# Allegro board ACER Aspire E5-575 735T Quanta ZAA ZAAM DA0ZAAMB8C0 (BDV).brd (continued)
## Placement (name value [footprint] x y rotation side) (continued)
C4682  gka@0.1u/16v_4  [C0402]  223.07 118.13 180 top
C4683  gka@1u/6.3v_4  [C0402]  208.21 113.3 270 bottom
C4684  gka@1u/6.3v_4  [C0402]  223.07 116.1 0 top
C4685  *gka@0.1u/16v_4  [C0402]  222.94 136.42 180 top
C4686  gka@0.1u/16v_4  [C0402]  212.78 113.3 270 bottom
C4687  gka@0.1u/16v_4  [C0402]  211.64 113.3 270 bottom
C4688  gka@1u/6.3v_4  [C0402]  223.07 119.15 0 bottom
C4689  gka@10u/6.3v_6  [C0603]  222.94 124.1 270 bottom
C4690  gka@1u/6.3v_4  [C0402]  219.64 131.97 0 top
C4691  gka@1u/6.3v_4  [C0402]  208.21 113.3 270 top
C4692  gka@1u/6.3v_4  [C0402]  222.94 147.72 0 top
C4693  gka@1u/6.3v_4  [C0402]  209.48 133.37 180 top
C4694  gka@0.047u/10v_4  [C0402]  223.07 117.11 180 top
C4695  gka@0.047u/10v_4  [C0402]  223.07 126 180 bottom
C4696  gka@0.047u/10v_4  [C0402]  207.45 133.37 0 top
C4697  gka@1u/6.3v_4  [C0402]  217.99 151.66 90 top
C4698  gka@0.1u/16v_4  [C0402]  223.07 127.02 180 top
C4699  gka@0.1u/16v_4  [C0402]  219.39 113.3 90 top
C4700  gka@0.1u/16v_4  [C0402]  215.58 133.37 180 top
C4701  gka@330u/2v_7343  [CC7343]  221.7 112.23 180 bottom
C4702  gka@0.1u/16v_4  [C0402]  215.58 131.97 180 top
C4703  gka@1u/6.3v_4  [C0402]  209.48 131.97 180 top
C4704  gka@0.1u/16v_4  [C0402]  223.07 127.02 180 bottom
C4705  gka@0.1u/16v_4  [C0402]  222.94 147.72 180 bottom
C4706  gka@10u/6.3v_6  [C0603]  223.32 135.02 180 top
C4707  gka@0.1u/16v_4  [C0402]  223.07 126 180 top
C4708  gka@0.047u/10v_4  [C0402]  222.05 131.97 180 top
C4709  *gka@0.1u/16v_4  [C0402]  209.35 113.3 90 top
C4711  100u/6.3v_12  [C1206]  208.34 21.74 90 bottom
C4712  100u/6.3v_1206  [C1206]  208.34 26.44 90 bottom
C4713  470p/50v_4  [C0402]  212.02 26.31 0 bottom
C4714  1u/6.3v_4  [C0402]  215.07 28.34 270 bottom
C4715  0.1u/16v_4  [C0402]  209.99 27.96 90 bottom
C4719  ev@0.1u/16v_4  [C0402]  206.43 157.63 180 top
C4721  ev@22u/6.3v_6  [C0603]  206.81 156.36 180 top
C4723  *22p/50v_4  [C0402]  150.68 101.37 180 bottom
C4726  *22p/50v_4  [C0402]  175.82 47.9 270 bottom
C4732  47u/6.3v_8  [C0805]  91.62 115.21 90 top
C4733  *10p/50v_4  [C0402]  170.24 81.43 270 bottom
C4734  *10u/6.3v_4  [C0402]  169.22 81.43 270 bottom
C4735  *0.1u/16v_4  [C0402]  171.51 81.43 270 bottom
C4736  *10p/50v_4  [C0402]  169.98 83.08 0 bottom
C4737  *10p/50v_4  [C0402]  171.51 84.98 90 bottom
C4748  0.1u/16v_4  [C0402]  28 67.71 0 top
C4749  0.1u/16v_4  [C0402]  21.39 71.14 0 bottom
C4750  0.1u/16v_4  [C0402]  21.65 68.6 0 bottom
C4751  0.1u/16v_4  [C0402]  21.52 63.9 270 top
C4752  0.1u/16v_4  [C0402]  22.54 63.9 270 top
C4753  4.7u/6.3v_4  [C0402]  21.39 72.26 180 bottom
C4754  2.2u/6.3v_4  [C0402]  20.4 63.9 270 top
C4762  tyc@0.1u/25v/x5r_4  [C0402]  21.01 120.67 180 bottom
C4763  tyc@0.1u/25v/x5r_4  [C0402]  21.01 121.56 180 bottom
C4764  tyc@0.1u/25v_4  [C0402]  11.11 116.33 0 top
C4765  tyc@10u/6.3v/x5r_6  [C0603]  28.5 108.73 90 top
C4766  tyc@10u/6.3v/x5r_6  [C0603]  36.76 109.75 0 top
C4767  tyc@0.1u/25v_4  [C0402]  19.49 112.54 90 top
C4768  tyc@0.1u/25v_4  [C0402]  11.11 115.36 0 top
C4769  tyc@10u/6.3v/x5r_6  [C0603]  36.76 108.48 0 top
C4770  tyc@0.1u/25v/x5r_4  [C0402]  21.14 116.73 180 bottom
C4771  tyc@0.1u/25v/x5r_4  [C0402]  21.14 117.62 180 bottom
C4772  tyc@150u/6.3v_3528  [C3528]  37.65 106.06 180 top
C4773  tyc@0.1u/16v_4_x7r  [C0402]  27.23 118.51 0 top
C4774  tyc@0.1u/16v_4_x7r  [C0402]  35.11 120.67 180 top
C4775  tyc@10u/6.3v_6_x5r  [C0603]  27.62 117.37 0 top
C4776  tyc@0.1u/16v_4_x7r  [C0402]  37.52 121.05 0 top
C4777  tyc@0.1u/16v_4_x7r  [C0402]  37.52 120.16 0 top
C4778  tyc@0.1u/16v_4_x7r  [C0402]  37.52 122.83 0 top
C4779  tyc@0.1u/16v_4_x7r  [C0402]  37.52 121.94 0 top
C4780  tyc@0.1u/16v_4_x7r  [C0402]  37.52 118.13 0 top
C4781  tyc@0.1u/16v_4_x7r  [C0402]  35.74 116.99 0 top
C4782  *ioac@0.1u/16v_4  [C0402]  48.57 70.38 90 top
C4783  0.1u/16v_4  [C0402]  22.92 52.09 0 top
C4784  0.1u/16v_4_x7r  [C0402]  17.07 43.33 270 top
C4785  0.1u/16v_4_x7r  [C0402]  20.5 55.14 270 top
C4786  0.1u/16v_4_x7r  [C0402]  18.34 55.14 270 top
C4787  0.1u/16v_4_x7r  [C0402]  22.92 53.87 180 top
C4788  *220p/50v_4  [C0402]  195.66 23.64 270 bottom
C4789  *220p/50v_4  [C0402]  194.52 23.64 270 bottom
C4790  *220p/50v_4  [C0402]  193.35 23.64 270 bottom
C4791  *220p/50v_4  [C0402]  192.21 23.64 270 bottom
C4792  *220p/50v_4  [C0402]  177.35 23.64 270 bottom
C4793  *220p/50v_4  [C0402]  176.21 23.64 270 bottom
C4794  *220p/50v_4  [C0402]  175.06 23.64 270 bottom
C4795  *220p/50v_4  [C0402]  173.92 23.64 270 bottom
C4796  *220p/50v_4  [C0402]  181.92 23.64 270 bottom
C4797  *220p/50v_4  [C0402]  180.78 23.64 270 bottom
C4798  *220p/50v_4  [C0402]  179.63 23.64 270 bottom
C4799  *220p/50v_4  [C0402]  178.49 23.64 270 bottom
C4800  *220p/50v_4  [C0402]  186.49 23.64 270 bottom
C4801  *220p/50v_4  [C0402]  185.35 23.64 270 bottom
C4802  *220p/50v_4  [C0402]  184.21 23.64 270 bottom
C4803  *220p/50v_4  [C0402]  183.06 23.64 270 bottom
C4804  *220p/50v_4  [C0402]  200.23 23.64 270 bottom
C4805  *220p/50v_4  [C0402]  199.07 23.64 270 bottom
C4806  *220p/50v_4  [C0402]  197.95 23.64 270 bottom
C4807  *220p/50v_4  [C0402]  196.78 23.64 270 bottom
C4808  *220p/50v_4  [C0402]  191.06 23.64 270 bottom
C4809  *220p/50v_4  [C0402]  189.92 23.64 270 bottom
C4810  *220p/50v_4  [C0402]  188.78 23.64 270 bottom
C4811  *220p/50v_4  [C0402]  187.64 23.64 270 bottom
C4812  ev@10u/6.3v_4  [C0402]  181.59 136.65 0 top
C4813  ev@10u/6.3v_4  [C0402]  186.21 131.95 180 top
C4814  ev@10u/6.3v_4  [C0402]  182.05 127.78 270 top
C4815  *ev@10u/6.3v_4  [C0402]  187 128.04 270 top
C4816  22u/6.3v_6  [C0603]  86.8 113.18 270 bottom
C4817  tyc_emi@100p/50v_4  [C0402]  28.73 106.42 90 top
C4818  tyc_emi@100p/50v_4  [C0402]  11.11 117.29 180 top
C4819  *1000p/50v_4  [C0402]  116.01 33.8 90 top
CN2  *aces_88511-180n  [88511-180N-18P-L]  169.35 94.13 0 top
CN4  sd-card  [SDCARD-PSDAT4-11GLBS1NN4H4-11P]  35.49 19.6 0 top
CN5  lvds_conn  [GS12401-1011-40P-R-NH-SMT]  121.5 174.4 45 bottom
CN6  kbl@kb_backlight  [50591-00401-001-4P-L]  224.2 134.09 270 bottom
CN7  crt conn  [DSUB-95-0005-01-15P]  6.62 79.15 90 bottom
CN8  fan_3p  [HS8803F-3P-L]  57.87 120.4 90 bottom
CN9  c185q2-11311-l  [SATA-C185Q2-11311-L-13P-R]  234.02 101.31 270 bottom
CN10  wlan_ngff conn  [NGFF-NASE0-S6701-TS48-KE-SMT]  196.3 182.75 270 bottom
CN11  rj45  [RJ45-JM361C-HP34AA03-9H-8P]  2.65 104.4 90 bottom
CN12  hdmi connector  [HDMI-10444-19001-19P]  3.35 50.5 90 bottom
CN13  usb3.0 conn  [UB3-YUSB0021-P001A-9P-SMT]  6.82 31.8 90 bottom
CN14  hdd_conn(on board)  [SATA-C166FQ-12208-L-22P-R]  229.5 44.65 270 bottom
CN16  usb3.0 conn  [UB3-YUSB0021-P001A-9P-SMT]  6.82 15.2 90 bottom
CN17  tp_conn  [50503-0080N-001-8P-L]  122.5 14.95 180 bottom
CN18  spk_conn_4p  [50271-0040N-V01-4P-L]  82.59 12 270 bottom
CN20  kbl15@kb_conn  [196153-28021-3-28P-L]  164.92 12.65 180 bottom
CN23  ssd@ssd_ngff_conn  [NGFF-NASM0-S6701-TS50-KM-SMT]  165.5 98.15 180 bottom
CN95  fpd@conn_aop  [196241-08021-3-8P-L]  110.5 13.45 180 bottom
CN2019  kbl17@kb_conn  [196153-28021-3-28P-L]  186.48 19.17 180 bottom
CN2020  db_conn  [51619-0260N-001-26P-L]  213.85 16.4 270 bottom
CN2021  tyc@usb_type_c  [UB31-DX07B024XJ1AR1000-24P-SMT]  6.6 119.9 90 bottom
D1  1n4148ws  [DSM]  111.44 152.89 180 bottom
D2  tvs/6pf_4  [C0402]  86.42 85.87 180 bottom
D3  tvs/6pf_4  [C0402]  82.73 86.63 180 bottom
D4  *tvs/6pf_4  [C0402]  133.66 80.66 0 bottom
D5  *tvs/6pf_4  [C0402]  131.63 81.81 180 bottom
D6  *az5125-01j  [C0402]  13.65 54.12 90 top
D7  bat54c  [SOT323_213-2_1-1_3-2N7002W]  75.88 50.06 90 top
D8  gs@rb500v-40  [DSM]  218.57 52.01 0 bottom
D9  1n4148ws  [DSM]  215.19 45.74 270 bottom
D10  1n4148ws  [DSM]  213.29 45.74 270 bottom
D11  *rb500v-40  [DSM]  163 28.98 0 bottom
D12  sdmk0340l-7-f  [DSMV]  192.72 35.45 90 bottom
D14  *rb500v-40  [DSM]  163 27.11 0 bottom
D15  *rb500v-40  [DSM]  192.12 46.12 270 bottom
D16  rb500v-40  [DSM]  190.09 46.12 270 bottom
D17  *rb500v-40  [DSM]  163 30.88 0 bottom
D18  rb500v-40  [DSM]  163 32.66 0 bottom
D20  *rb500v-40  [DSM]  163 34.56 0 bottom
D23  *vport_6  [C0603]  71.3 10.94 180 top
D24  *5.5v/25v/410p_4  [C0402]  61.65 16.53 0 top
D25  *5.5v/25v/410p_4  [C0402]  65.08 16.53 0 top
D26  *5.5v/25v/410p_4  [C0402]  53.02 16.53 0 top
D27  *5.5v/25v/410p_4  [C0402]  54.92 16.53 0 top
D28  *vport_6  [C0603]  72.95 14.12 90 top
D30  rb501v-40  [DSM]  21.27 41.29 0 top
D31  rb501v-40  [DSM]  16.44 41.25 0 top
D34  *vport_6  [C0603]  152.2 18.18 270 bottom
D35  gs@rb500v-40  [DSM]  223.02 52.05 180 bottom
D4000  gc6@bat54cw_200ma  [UMT_213-3-1_3]  227.11 113.66 180 top
D4001  *rb500v-40  [DSM]  159.95 23.43 0 bottom
D4002  *vport_6  [C0603]  172.65 23.51 270 bottom
D4012  *tvs/6pf_4  [C0402]  169.98 84.22 0 bottom
D4013  *tvs/6pf_4  [C0402]  172.9 84.98 90 bottom
D4014  *rb500v-40  [DSM]  159.95 25.34 0 bottom
D4015  varistor_4  [C0402]  183.34 45.61 90 bottom
EC35  *120p/50v_4  [C0402]  146.87 56.92 0 top
EC36  *120p/50v_4  [C0402]  129.72 67.33 270 bottom
EC37  *0.1u/16v_4  [C0402]  124.52 67.58 270 bottom
EC38  *0.1u/16v_4  [C0402]  120.58 67.08 0 bottom
EC39  *120p/50v_4  [C0402]  117.02 66.31 0 bottom
EC40  *120p/50v_4  [C0402]  147 40.28 0 top
EC41  *0.1u/16v_4  [C0402]  110.55 67.84 0 top
EC42  *120p/50v_4  [C0402]  99.62 67.08 270 top
EC43  *120p/50v_4  [C0402]  89.85 65.3 270 top
EC44  *120p/50v_4  [C0402]  130.99 39.9 180 bottom
EC45  *120p/50v_4  [C0402]  134.8 39.9 0 bottom
EC46  *120p/50v_4  [C0402]  115.12 39.9 0 bottom
EC47  *120p/50v_4  [C0402]  111.44 39.9 180 bottom
EC48  *120p/50v_4  [C0402]  105.21 40.02 0 bottom
EC49  120p/50v_4  [C0402]  101.15 40.02 180 bottom
EC50  *0.1u/16v_4  [C0402]  87.18 41.04 180 bottom
EC51  tyc@az5725-01f  [ESD-1X0_6-2P]  11.23 116.73 180 bottom
EC52  *az5725-01f  [ESD-1X0_6-2P]  113.09 17.93 180 bottom
EC53  *az5725-01f  [ESD-1X0_6-2P]  113.09 19.32 180 bottom
HOLE1  *hg-c354d134p2  [HG-C354D134P2]  12.5 3.6 0 top
HOLE2  *hg-c354d134p2  [HG-C354D134P2]  76.2 3.6 0 top
HOLE3  *hg-c354d134p2  [HG-C354D134P2]  11.6 63.9 0 top
HOLE4  *hg-c354d134p2  [HG-C354D134P2]  217.5 3.6 0 top
HOLE6  *o-zab-2  [O-ZAB-2]  133.57 189.2 0 top
HOLE7  *hg-tc354ic236bc236d118p2  [HG-TC354IC236BC236D118P2]  231 164.4 0 top
HOLE8  h-c236i156d140p2  [H-C236I156D140P2]  161.11 153.04 180 bottom
HOLE9  h-c236d140p2  [H-C236D140P2]  203.32 110.84 180 bottom
HOLE10  *h-tc236ic236bc256d161p2  [H-TC236IC236BC256D161P2]  146.38 94.29 180 bottom
HOLE11  *h-tc236ic236bc256d161p2  [H-TC236IC236BC256D161P2]  94.42 94.29 180 bottom
HOLE12  *h-tc236ic236bc256d161p2  [H-TC236IC236BC256D161P2]  120.4 139.29 180 bottom
HOLE13  h-c256d161p2  [H-C256D161P2]  165.5 57.9 180 bottom
HOLE14  h-c256d161p2  [H-C256D161P2]  165.5 39.9 180 bottom
HOLE15  h-c256d161p2  [H-C256D161P2]  165.5 19.9 180 bottom
HOLE16  h-tc217ic197bc197d126p2  [H-TC217IC197BC197D126P2]  224.55 182.75 180 bottom
HOLE17  *hg-zab-2  [HG-ZAB-2]  225.5 92.4 0 top
HOLE18  *hg-zab-2  [HG-ZAB-2]  73.5 83.4 0 top
HOLE19  *h-zab-5  [H-ZAB-5]  12 127.9 0 top
HOLE20  *h-c87d87n  [H-C87D87N]  232.75 83.4 0 top
HOLE21  *h-o146x87d146x87n  [H-O146X87D146X87N]  225.65 28.86 0 top
HOLE22  *o-zaa-1  [O-ZAA-1]  186.75 12.65 0 top
HOLE23  *hg-c315d134p2  [HG-C315D134P2]  140.58 8.05 0 top
HOLE24  *hg-c315d134p2  [HG-C315D134P2]  161.45 7.05 0 top
HOLE25  *h-c217d217n  [H-C217D217N]  216.5 182.67 0 top
J1  *jump  [JOPEN25X30_S]  78.77 19.25 0 bottom
JDIM1  ddr4-dimm0_h=8_rvs  [DDR4-D4AS0-26001-1P52-STD-SMT]  116.1 47.3 0 bottom
JDIM2  ddr4-dimm0_h=4_rvs  [DDR4-D4AR0-26001-1P52-RVS-SMT]  116.1 59.5 180 bottom
L4  60ohm@100mhz_6  [R0603]  25.96 63.52 270 top
L5  blm15bb220sn1d_6  [R0603]  14.28 75.84 0 top
L6  blm15bb220sn1d_6  [R0603]  14.28 73.81 0 top
L7  blm15bb220sn1d_6  [R0603]  13.52 71.77 0 top
L11  blm15ag121sn1d(120,500ma)_4  [R0402]  166.3 27.96 180 bottom
L12  blm15ag121sn1d(120,500ma)_4  [R0402]  168.59 32.53 90 bottom
L13  pby160808t-600y-n(60,3a)  [R0603]  197.54 48.03 90 bottom
L16  hcb2012kf220t60/6a/22ohm_8  [R0805]  210.11 35.45 0 bottom
L18  hcb1608kf-121t30_3a  [R0603]  196.78 40.28 0 bottom
L19  *short_6  [S0603]  135.06 14.75 90 bottom
L22  blm15ag121sn1d(120,500ma)_4  [R0402]  185.86 45.61 270 bottom
L69  *tyc@dlp11sn900hl2l  [CHOKE-DLP11SN900HL2L-4P-1]  18.34 114.7 180 top
L4100  sp@hcb1005kf-330t30  [R0402]  164.65 140.99 0 top
L4200  ev@hcb1005kf-330t30  [R0402]  173.79 123.84 90 top
L4201  ev@blm15px181sn1d_1.5a  [R0402]  168.2 123.08 270 top
L4206  *sp@hcb1005kf-330t30  [R0402]  164.65 139.85 0 top
L4207  ev@hcb1005kf-330t30  [R0402]  206.43 158.64 180 top
L4208  60ohm@100mhz_6  [R0603]  21.27 67.46 0 bottom
L4209  tyc@blm18pg181sn1d_0.5a  [R0603]  27.62 116.1 0 top
LED1  led_amber/blue  [LEDLTST-S326KGJRKT-3P-SMT]  55.5 4.4 180 top
LED2  led_amber/blue  [LEDLTST-S326KGJRKT-3P-SMT]  63.5 4.4 180 top
MR1  ah9249ntr-g1  [SOT23_123-2_8-1_9]  87.5 2.5 90 top
NOREF  -  []  109.91 -49.26 0 top
NOREF#2  -  [unnamed#2]  208.36 10.64 0 top
NOREF#3  -  [unnamed#2]  229.22 176.88 0 top
NOREF#4  -  []  72.19 115.89 0 top
NOREF#5  -  []  60.99 113.18 0 top
NOREF#6  -  [unnamed#2]  28.02 125.8 0 top
NOREF#7  -  []  59.11 -89.9 0 top
NOREF#8  -  [unnamed#2]  17.1 9.29 180 bottom
NOREF#9  -  []  27.41 14.29 180 bottom
NOREF#10  -  [unnamed#2]  208.36 10.64 180 bottom
NOREF#11  -  [unnamed#2]  28.02 125.8 180 bottom
PAD1  *spad-zab-1np  [SPAD-ZAB-1NP]  176.23 185.2 0 top
PAD2  *spad-zab-2np  [SPAD-ZAB-2NP]  242.4 191.63 0 top
PAD3  *spad-re157x488np  [SPAD-RE157X488NP]  203.09 74.81 0 top
PAD4  *spad-re157x1282np  [SPAD-RE157X1282NP]  194.07 24.33 0 top
PAD5  *spad-zab-3np  [SPAD-ZAB-3NP]  175.65 84.17 0 top
PAD6  *spad-c298np  [SPAD-C298NP]  140.65 84.17 0 top
PAD7  *spad-re157x491np  [SPAD-RE157X491NP]  86.19 72.78 0 top
PAD8  *spad-c298np  [SPAD-C298NP]  114.15 84.17 0 top
PAD9  *spad-c276np  [SPAD-C276NP]  44.6 41.15 0 top
PAD10  *spad-re157x1267np  [SPAD-RE157X1267NP]  86.19 24.14 0 top
PAD11  *spad-re531x205np  [SPAD-RE531X205NP]  216.34 189.9 0 top
PAD12  *spad-re157x315np  [SPAD-RE157X315NP]  194.09 64.62 0 top
PAD13  *spad-c197np  [SPAD-C197NP]  186.24 51.84 180 bottom
PAD14  *o-zab-1  [O-ZAB-1]  108.96 167.65 0 top
PC1  *0.01u/50v_4  [C0402]  157.36 167.84 90 top
PC2  0.1u/50v_6  [C0603]  162.52 186.02 180 top
PC3  100p/50v_4  [C0402]  153.47 186.93 270 top
PC4  *680p/50v_6  [C0603]  169.25 180.16 90 bottom
PC5  0.1u/50v_6  [C0603]  160.08 186.46 90 top
PC6  100p/50v_4  [C0402]  152.51 186.93 270 top
PC7  *100p/50v_4  [C0402]  134.83 170.99 270 top
PC8  *47p/50v_4  [C0402]  149.97 168.89 90 top
PC9  *47p/50v_4  [C0402]  152.79 168.87 90 top
PC10  1u/6.3v_4  [C0402]  138.74 167.81 180 top
PC11  *0.01u/50v_4  [C0402]  136.4 168.78 270 top
PC12  *0.01u/50v_4  [C0402]  136.43 166.92 90 top
PC13  0.1u/50v_6  [C0603]  220.35 187.14 270 bottom
PC14  0.1u/25v_4  [C0402]  140.93 167.96 90 top
PC15  470p/50v_4  [C0402]  139.05 169.23 90 top
PC16  220p/50v_4  [C0402]  137.9 169.23 90 top
PC17  *gt3@0.022u/25v_4  [C0402]  144.2 170.99 90 top
PC18  *gt3@0.022u/25v_4  [C0402]  143.19 170.99 90 top
PC19  2200p/50v_4  [C0402]  142.12 170.99 90 top
PC20  0.022u/25v_4  [C0402]  140.63 171.33 0 top
PC21  33p/50v_4  [C0402]  136.91 170.99 270 top
PC22  330p/50v_4  [C0402]  136.48 174.62 270 bottom
PC23  330p/50v_4  [C0402]  144.74 174.95 180 top
PC24  33p/50v_4  [C0402]  141.19 177.15 180 bottom
PC25  *0.01u/50v_4  [C0402]  149.66 177.95 0 top
PC26  1000p/50v_4  [C0402]  147.22 177.54 270 top
PC27  *0.01u/50v_4  [C0402]  144.74 179.19 0 top
PC28  560p/50v_4  [C0402]  144.71 178.05 180 top
PC29  0.01u/50v_4  [C0402]  147.4 172.41 270 top
PC30  10n/50v_4  [C0402]  145.52 181.07 90 top
PC31  0.1u/25v_4  [C0402]  146.49 181.1 270 top
PC32  0.1u/25v_4  [C0402]  133.91 175.28 90 bottom
PC33  0.1u/25v_4  [C0402]  147.17 184.58 0 top
PC34  2200p/50v_4  [C0402]  145.92 182.51 0 top
PC35  0.1u/25v_4  [C0402]  134.63 178.43 0 top
PC36  330p/50v_4  [C0402]  141.36 179.12 90 bottom
PC37  33p/50v_4  [C0402]  139.43 179.12 270 bottom
PC38  0.047u/10v_4  [C0402]  139.25 183.41 0 bottom
PC39  0.015u/50v_4  [C0402]  139.25 182.44 180 top
PC40  2200p/50v_4  [C0402]  137.62 183.1 90 bottom
PC41  *680p/50v_4  [C0402]  142.22 184.83 270 top
PC42  1000p/50v_4  [C0402]  142.42 184.93 270 bottom
PC43  0.1u/25v_4  [C0402]  138.03 185.59 0 bottom
PC44  *0.01u/50v_4  [C0402]  142.42 186.71 270 bottom
PC45  0.01u/50v_4  [C0402]  141.26 187.29 90 top
PC46  *0.01u/50v_4  [C0402]  144.28 184.88 270 top
PC47  10u/25v_8  [C0805]  124.63 159.14 270 top
PC48  2200p/50v_6  [C0603]  122.84 158.97 90 bottom
PC49  *gt3@10u/25v_8  [C0805]  134.61 158.5 270 top
PC50  *gt3@2200p/50v_6  [C0603]  132.91 158.73 90 top
PC51  2200p/50v_6  [C0603]  138.61 157.73 90 top
PC52  10u/25v_8  [C0805]  142.88 159.07 270 top
PC53  2200p/50v_6  [C0603]  158.58 159.61 90 bottom
PC54  10u/25v_8  [C0805]  156.88 159.28 270 bottom
PC55  1000p/50v_4  [C0402]  120.33 156.23 270 top
PC56  *gt3@1000p/50v_4  [C0402]  128.07 155.77 270 top
PC57  1000p/50v_4  [C0402]  149.43 154.71 0 top
PC58  1000p/50v_4  [C0402]  141.57 155.07 180 top
PC59  330u/2v_7343  [CC7343]  135.57 141.88 180 bottom
PC61  *0.1u/50v_6  [C0603]  48.34 45.05 270 top
PC65  10u/6.3v_6  [C0603]  48.06 51.58 180 top
PC70  *1u/16v_6  [C0603]  48.06 52.98 0 top
PC71  10u/6.3v_6  [C0603]  36.05 47.19 90 top
PC74  0.1u/50v_6  [C0603]  48.06 50.18 0 top
PC75  *0.1u/50v_6  [C0603]  164.52 63.04 0 bottom
PC76  10u/6.3v_6  [C0603]  159.85 62.3 180 bottom
PC77  *1u/16v_6  [C0603]  157.18 62.68 180 bottom
PC78  0.1u/50v_6  [C0603]  159.85 60.78 0 bottom
PC79  1u/6.3v_4  [C0402]  156.88 61.11 270 bottom
PC80  10u/6.3v_6  [C0603]  156.67 73.38 270 bottom
PC81  1u/6.3v_4  [C0402]  49.05 54.15 0 top
PC83  1u/25v_4  [C0402]  64.06 18.38 0 bottom
PC84  *0.1u/16v_4  [C0402]  66.73 21.58 180 bottom
PC85  0.1u/16v_4  [C0402]  62.67 23.82 270 bottom
PC86  ev@10u/25v_8  [C0805]  176.41 71.29 0 bottom
PC87  *0.1u/16v_4  [C0402]  64.7 20.09 0 top
PC88  0.1u/16v_4  [C0402]  64.7 21.1 0 top
PC89  0.047u/10v_4  [C0402]  67.49 72.54 90 bottom
PC90  1u/25v_4  [C0402]  64.01 23.44 0 bottom
PC91  0.1u/16v_4  [C0402]  62.64 17.98 90 bottom
PC92  ev@0.047u/10v_4  [C0402]  216.19 175.84 0 bottom
PC97  10u/6.3v_6  [C0603]  61.37 24.28 270 bottom
PC98  1000p/50v_4  [C0402]  60.64 20.34 0 bottom
PC99  *gt3@10u/25v_8  [C0805]  49.03 78.71 270 top
PC100  *gt3@2200p/50v_4  [C0402]  55.43 80.16 270 bottom
PC101  *2.2n/50v_4  [C0402]  69.3 100.73 180 top
PC102  0.1u/50v_6  [C0603]  48.67 109 270 top
PC103  2200p/50v_4  [C0402]  47.55 35.45 90 top
PC104  0.1u/50v_6  [C0603]  50.78 116.61 0 top
PC105  10u/6.3v_6  [C0603]  61.32 17.39 90 bottom
PC106  1u/25v_4  [C0402]  59.39 52.09 0 bottom
PC107  *0.1u/16v_4  [C0402]  61.68 55.57 180 bottom
PC108  0.1u/16v_4  [C0402]  57.84 56.74 180 bottom
PC109  *ev@1u/10v_4  [C0402]  52.15 70.12 180 top
PC110  *ev@22p/50v_4  [C0402]  194.42 56.76 0 bottom
PC111  0.1u/16v_4  [C0402]  61.68 54.55 180 bottom
PC112  *0.1u/16v_4  [C0402]  61.7 53.49 180 bottom
PC113  *ev@2.2n/50v_4  [C0402]  195 108.35 180 bottom
PC114  0.1u/16v_4  [C0402]  57.66 52.09 180 bottom
PC115  0.1u/50v_6  [C0603]  162.52 187.47 0 top
PC116  0.47u/25v_6  [C0603]  161.96 184.6 0 top
PC117  2200p/50v_6  [C0603]  166.11 180.49 0 bottom
PC118  10u/25v_8  [C0805]  166.04 180.26 180 top
PC119  47n/50v_6  [C0603]  161.77 183.2 180 top
PC120  10u/25v_8  [C0805]  163.89 171.98 90 bottom
PC121  2200p/50v_6  [C0603]  162.29 171.6 270 bottom
PC122  2.2u/10v_6  [C0603]  160.56 178.89 90 top
PC123  0.01u/50v_4  [C0402]  158.91 178.61 90 top
PC124  2200p/50v_6  [C0603]  229.32 183.79 270 top
PC125  *100p/50v_4  [C0402]  160.48 174.92 90 top
PC126  0.1u/50v_6  [C0603]  157.61 172.89 0 top
PC127  10u/25v_8  [C0805]  165.92 172.61 90 bottom
PC128  0.1u/50v_6  [C0603]  230.79 183.79 270 top
PC129  3300p/50v_4  [C0402]  135.49 170.56 0 bottom
PC130  0.1u/25v_4  [C0402]  159.09 174.67 90 top
PC131  0.1u/25v_4  [C0402]  157.21 174.06 180 top
PC132  0.1u/25v_4  [C0402]  155.61 173.91 270 top
PC133  1n/50v_4  [C0402]  210.24 191.76 90 bottom
PC134  sp@0.1u/25v_4  [C0402]  140.7 172.89 180 bottom
PC135  2200p/50v_4  [C0402]  146.18 175.36 90 top
PC136  47n/50v_6  [C0603]  211.54 190.67 270 bottom
PC137  1u/25v_4  [C0402]  59.57 56.76 0 bottom
PC138  33u/25v_6x4.5  [ECAP6_3X6_1-7_2]  130.71 168.83 0 bottom
PC139  2200p/50v_4  [C0402]  143.29 184.86 270 top
PC140  2200p/50v_6  [C0603]  211.31 178.81 270 bottom
PC141  0.1u/50v_6  [C0603]  212.73 178.81 90 bottom
PC142  0.1u/50v_6  [C0603]  122.79 163.82 90 bottom
PC143  *gt3@0.1u/50v_6  [C0603]  130.99 163.67 90 bottom
PC144  0.1u/50v_6  [C0603]  142.37 163.47 90 bottom
PC145  0.1u/50v_6  [C0603]  153.45 163.7 90 bottom
PC146  4.7u/10v_6  [C0603]  118.04 162.96 90 bottom
PC147  *gt3@4.7u/10v_6  [C0603]  126.52 159.94 270 bottom
PC148  10u/25v_8  [C0805]  124.67 159.13 270 bottom
PC149  4.7u/10v_6  [C0603]  136.48 159.68 270 bottom
PC150  0.1u/50v_6  [C0603]  122.84 158.97 90 top
PC151  4.7u/10v_6  [C0603]  148.44 159.96 270 bottom
PC152  *gt3@10u/25v_8  [C0805]  134.61 158.5 270 bottom
PC153  *gt3@0.1u/50v_6  [C0603]  132.89 158.73 90 bottom
PC154  0.1u/50v_6  [C0603]  142.65 158.77 90 bottom
PC155  10u/25v_8  [C0805]  144.39 159.06 270 bottom
PC156  0.1u/50v_6  [C0603]  160 159.61 90 bottom
PC157  10u/25v_8  [C0805]  154.84 159.28 270 bottom
PC158  *gt3@330u/2v_7343  [CC7343]  108.35 141.94 180 bottom
PC159  0.1u/16v_4  [C0402]  133.66 145.18 90 top
PC160  *gt3@0.1u/16v_4  [C0402]  133.66 145.18 90 bottom
PC161  0.1u/16v_4  [C0402]  133.15 138.2 270 bottom
PC162  330u/2v_7343  [CC7343]  144.61 149.88 90 bottom
PC163  330u/2v_7343  [CC7343]  108.27 137.01 180 bottom
PC164  22u/6.3v_8  [C0805]  129.72 137.94 270 bottom
PC165  22u/6.3v_8  [C0805]  156.17 146.98 180 bottom
PC166  *gt3@22u/6.3v_8  [C0805]  129.47 142.01 90 bottom
PC167  *gt3@22u/6.3v_8  [C0805]  111.05 140.86 180 top
PC168  22u/6.3v_8  [C0805]  131.76 137.94 270 bottom
PC169  22u/6.3v_8  [C0805]  156.19 144.95 180 bottom
PC170  22u/6.3v_8  [C0805]  125.41 142.01 90 bottom
PC171  0.1u/16v_4  [C0402]  150.27 142.08 90 bottom
PC172  22u/6.3v_8  [C0805]  127.44 142.01 90 bottom
PC173  10u/6.3v_6  [C0603]  56.27 57.73 270 bottom
PC174  10u/6.3v_6  [C0603]  55.96 51.25 90 bottom
PC175  1000p/50v_4  [C0402]  60.64 21.33 0 bottom
PC176  1000p/50v_4  [C0402]  55.81 53.87 0 bottom
PC177  1000p/50v_4  [C0402]  55.81 54.88 0 bottom
PC178  *ev@0.01u/50v_4  [C0402]  203.1 55.98 270 bottom
PC179  ev@0.1u/50v_6  [C0603]  176.49 73.15 180 bottom
PC180  0.1u/16v_4  [C0402]  39.93 93.87 90 top
PC181  10u/25v_8  [C0805]  56.19 62.58 90 top
PC182  ev@0.22u/25v_6  [C0603]  196.91 63.75 180 bottom
PC183  ev@1000p/50v_6  [C0603]  191.57 71.62 180 top
PC184  ev@2200p/50v_4  [C0402]  213.34 68.14 180 bottom
PC185  1u/25v_4  [C0402]  36 96.79 270 top
PC186  ev@330u/2v_7343  [CC7343]  208.57 87.8 0 bottom
PC187  *ev@1u/10v_4  [C0402]  206.94 51.96 0 bottom
PC188  ev@1000p/50v_6  [C0603]  197.87 74.42 0 top
PC189  0.1u/16v_4  [C0402]  35.87 98.32 0 top
PC190  ev@10u/6.3v_8  [C0805]  184.26 95.88 0 top
PC191  ev@0.1u/16v_4  [C0402]  208.9 93.29 180 bottom
PC192  ev@10u/6.3v_8  [C0805]  208.79 91.56 180 bottom
PC193  ev@0.1u/16v_4  [C0402]  206.3 102 180 top
PC194  22u/6.3v_8  [C0805]  67.06 67.1 0 top
PC195  ev@1u/10v_4  [C0402]  199.17 64.43 270 bottom
PC196  *0.1u/16v_4  [C0402]  42.09 52.93 90 top
PC197  *680p/50v_6  [C0603]  59.09 59.56 0 top
PC198  *10u/6.3v_6  [C0603]  43.03 60.22 270 top
PC199  ev@4700p/25v_4  [C0402]  195.23 60.5 0 bottom
PC200  ev@2700p/50v_4  [C0402]  205.59 57.2 90 bottom
PC201  ev@330u/2v_7343  [CC7343]  185.48 96.03 180 bottom
PC202  0.1u/50v_6  [C0603]  47.76 60.27 90 top
PC203  *0.1u/16v_4  [C0402]  43.06 52.93 90 top
PC204  ev@330u/2.5v_6x4.2  [ECAP6_3X6_1-7_2]  185.65 101.98 0 bottom
PC205  22u/6.3v_8  [C0805]  69.45 59 90 top
PC206  ev@1u/10v_4  [C0402]  200.97 55.98 270 bottom
PC207  10u/6.3v_6  [C0603]  41.66 59.25 270 top
PC208  10u/6.3v_6  [C0603]  35.87 99.59 0 top
PC209  ev@2200p/50v_4  [C0402]  176.49 74.54 0 bottom
PC210  1000p/50v_4  [C0402]  39.17 100.86 270 top
PC211  ev@10u/25v_8  [C0805]  213.8 71.27 180 bottom
PC212  0.1u/16v_4  [C0402]  40.34 57.37 0 top
PC213  10u/25v_8  [C0805]  56.11 64.05 90 bottom
PC214  *0.1u/16v_4  [C0402]  37.9 93.87 90 top
PC215  0.1u/16v_4  [C0402]  67.09 68.6 0 bottom
PC216  22u/6.3v_8  [C0805]  67.06 67.1 0 bottom
PC217  1u/6.3v_4  [C0402]  49.49 57.55 270 top
PC218  0.033u/10v_4  [C0402]  39.63 55.37 0 top
PC219  22u/6.3v_8  [C0805]  68.05 57.37 90 bottom
PC220  ev@10u/25v_8  [C0805]  176.38 69.13 0 bottom
PC221  ev@22p/50v_4  [C0402]  195.23 59.51 0 bottom
PC222  *gt3@22uf/6.3v_6  [C0603]  52.21 94.7 0 bottom
PC223  *gt3@22uf/6.3v_6  [C0603]  52.58 92.68 0 top
PC224  *ev@33u/25v_6x4.5  [ECAP6_3X6_1-7_2]  217.07 84.53 270 bottom
PC225  *gt3@22uf/6.3v_6  [C0603]  52.26 96.22 0 bottom
PC226  *gt3@0.1u/16v_4  [C0402]  58.6 95.65 180 bottom
PC227  *ev@0.01u/50v_4  [C0402]  196.53 53.99 270 bottom
PC228  *gt3@10u/25v_8  [C0805]  51.31 80.08 270 top
PC229  *gt3@0.1u/25v_4  [C0402]  55.81 78.86 180 bottom
PC230  *gt3@1u/10v_4  [C0402]  57.16 82.9 270 bottom
PC231  *gt3@0.1u/50v_6  [C0603]  58.5 85.16 270 bottom
PC232  *10u/6.3v_6  [C0603]  160.46 50.06 270 bottom
PC233  10u/6.3v_6  [C0603]  162.62 44.72 180 bottom
PC234  22u/6.3v_6  [C0603]  61.75 93.21 270 bottom
PC235  *1000p/50v_4  [C0402]  63.2 70.91 90 top
PC236  *22u/6.3v_6  [C0603]  64.22 93.06 0 bottom
PC237  2200p/50v_6  [C0603]  61.27 76.6 0 top
PC238  10u/25v_8  [C0805]  59.44 74.09 90 bottom
PC239  22u/6.3v_6  [C0603]  60.38 93.21 270 bottom
PC240  0.47uf/4v_4  [C0402]  167.19 45.49 180 bottom
PC241  0.1u/16v_4  [C0402]  161.85 49.93 90 bottom
PC242  22u/6.3v_6  [C0603]  64.24 95.8 0 bottom
PC243  10u/6.3v_6  [C0603]  68.87 74.09 180 bottom
PC244  4.7u/6.3v_6  [C0603]  163.89 49.42 0 bottom
PC245  22u/6.3v_6  [C0603]  61.75 93.19 270 top
PC246  ev@0.01u/50v_4  [C0402]  209.78 175.94 90 top
PC247  *ev@68p/50v_4  [C0402]  204.68 177.54 180 bottom
PC248  22u/6.3v_6  [C0603]  64.22 94.41 0 bottom
PC249  ev@10u/6.3v_6  [C0603]  209.86 175.91 90 bottom
PC250  0.1u/16v_4  [C0402]  62.92 93.14 270 top
PC251  ev@0.1u/50v_6  [C0603]  213.47 69.49 0 bottom
PC252  ev@1u/6.3v_4  [C0402]  204.68 178.53 180 bottom
PC253  ev@0.22u/25v_6  [C0603]  202.8 63.7 0 bottom
PC254  ev@10u/25v_8  [C0805]  213.8 73.55 180 bottom
PC267  0.1u/25v_6  [C0603]  67.32 78.05 0 bottom
PC268  *22u/6.3v_6  [C0603]  60.38 93.19 270 top
PC269  *0.1u/25v_4  [C0402]  61.27 78 180 top
PC270  *680p/50v_6  [C0603]  64.06 81.43 90 top
PC271  *0.01u/25v_4  [C0402]  60.92 71.29 0 bottom
PC272  *0.047u/10v_4  [C0402]  65.54 70.86 90 bottom
PC273  ev@22u/6.3v_6  [C0603]  215.04 159.4 90 bottom
PC274  *ev@1000p/50v_4  [C0402]  221.8 178.33 180 bottom
PC275  *ev@22u/6.3v_6  [C0603]  224.44 166.29 270 bottom
PC276  ev@2200p/50v_6  [C0603]  221.8 173.5 270 top
PC277  ev@10u/25v_8  [C0805]  223.65 175.2 270 bottom
PC278  ev@22u/6.3v_6  [C0603]  223.93 161.16 180 bottom
PC279  ev@22u/6.3v_6  [C0603]  224.52 163.06 90 bottom
PC280  ev@10u/6.3v_6  [C0603]  215.09 174.62 0 bottom
PC281  ev@22u/6.3v_6  [C0603]  219.18 159.4 90 bottom
PC282  ev@22u/6.3v_6  [C0603]  217.79 159.4 90 bottom
PC283  0.1u/25v_4  [C0402]  53.04 63.39 90 top
PC284  *330u/2.5v_6x4.2  [ECAP6_3X6_1-7_2]  71.91 69.72 270 bottom
PC285  0.1u/25v_4  [C0402]  54.69 63.29 270 top
PC286  2200p/50v_4  [C0402]  57.21 68.8 90 bottom
PC287  ev@0.1u/16v_4  [C0402]  213.87 159.4 90 bottom
PC288  *ev@22u/6.3v_6  [C0603]  216.41 159.4 90 bottom
PC289  ev@0.1u/25v_6  [C0603]  215.09 171.9 180 bottom
PC290  *ev@680p/50v_6  [C0603]  219.26 171.85 180 top
PC291  *ev@0.1u/25v_4  [C0402]  223.7 172.99 90 top
PC292  *ev@0.01u/25v_4  [C0402]  223.55 177.31 180 bottom
PC293  *ev@0.047u/10v_4  [C0402]  218.14 177.74 270 bottom
PC300  *ev@0.1u/16v_4  [C0402]  204.65 173.43 180 bottom
PC301  *ev@22p/50v_4  [C0402]  204.65 174.52 0 bottom
PC302  ev@22u/6.3v_6  [C0603]  209.17 160.83 90 bottom
PC303  ev@0.1u/16v_4  [C0402]  210.57 160.85 270 bottom
PC304  *ev@2200p/50v_4  [C0402]  211.44 174.95 90 bottom
PC328  ev@330u/2.5v_6x4.2  [ECAP6_3X6_1-7_2]  208.59 100.73 180 bottom
PC6098  4.7u/6.3v_6  [C0603]  56.34 39.54 180 bottom
PC6100  0.1u/25v_4  [C0402]  48.8 39.33 180 top
PC6212  *33u/25v_6x4.5  [ECAP6_3X6_1-7_2]  216.97 99.97 270 bottom
PC6213  0.1u/50v_6  [C0603]  51.57 43.58 0 top
PC6214  2200p/50v_4  [C0402]  58.22 46.3 270 bottom
PC6215  0.1u/50v_6  [C0603]  51.24 33.78 180 top
PC6216  10u/25v_8  [C0805]  56.75 46.58 270 bottom
PC6218  2200p/50v_4  [C0402]  57.13 30.2 90 top
PC6219  10u/6.3v_6  [C0603]  48.42 38.02 180 top
PC6220  10u/25v_8  [C0805]  56.01 30.4 90 bottom
PC6221  *680p/50v_6  [C0603]  62.77 26.46 0 bottom
PC6222  *680p/50v_6  [C0603]  60.79 49.07 0 top
PC6224  220u/6.3v_6x4.2  [ECAP6_3X6_1-7_2]  72.65 55.01 270 bottom
PC6225  0.1u/50v_6  [C0603]  74.48 48.91 0 bottom
PC6226  0.1u/50v_6  [C0603]  67.42 37.52 180 bottom
PC6227  220u/6.3v_6x4.2  [ECAP6_3X6_1-7_2]  72.68 39.44 270 bottom
PC6228  1000p/50v_4  [C0402]  131.25 172.87 90 top
PC6229  *33u/25v_6x4.5  [ECAP6_3X6_1-7_2]  228.89 175.18 270 bottom
PC6230  22u/6.3v_6  [C0603]  78.59 98.34 270 bottom
PC6231  *22u/6.3v_6  [C0603]  79.94 97.17 90 bottom
PD1  pdz5.6b  [DSM]  151.39 169.37 270 top
PD2  pdz5.6b  [DSM]  154.19 169.35 270 top
PD3  p4smafj20a  [D-DO-214AC]  230.08 183.48 270 bottom
PD4  da2j10100l  [DSM]  42.3 109.09 0 top
PD8  sv1040  [D-TO277_213-6_1X4_3]  224.24 189.12 0 bottom
PJ1  50458-00801-v01  [50458-00801-V02-8P-L]  153.55 178.38 0 bottom
PJ3  power conn  [50320-0040N-001-4P-L]  238.42 191.12 290 bottom
PL1  6.8uh_7x7x3  [CHOKE-PCMC063T-3R3MN-SMT]  173.54 179.85 90 bottom
PL2  0.15uh_7x7x4  [CHOKE-PCMC063T-R82MN-4P-SMT]  119.64 151.2 270 bottom
PL3  *gt3@0.15uh_7x7x4  [CHOKE-PCMC063T-R82MN-4P-SMT]  128.73 151.12 270 bottom
PL4  0.15uh_7x7x4  [CHOKE-PCMC063T-R82MN-4P-SMT]  138.59 150.36 270 bottom
PL5  0.47uh_7x7x3  [CHOKE-PCMC063T-R82MN-4P-SMT]  150.78 148.43 270 bottom
PL9  ev@0.36uh_10x10x4  [CHOKE-ETQP4LR36WFC-SMT]  197.92 86.89 90 bottom
PL10  ev@0.36uh_10x10x4  [CHOKE-ETQP4LR36WFC-SMT]  186.52 86.86 90 bottom
PL11  1uh_7x7x3  [CHOKE-PCMC063T-3R3MN-SMT]  66.96 62.68 0 bottom
PL13  *gt3@0.68uh_7x7x3  [CHOKE-PCMC063T-3R3MN-SMT]  55.84 90.24 90 bottom
PL14  ev@1uh_7x7x3  [CHOKE-PCMC063T-3R3MN-SMT]  211.92 166.26 270 bottom
PL15  0.68uh_7x7x3  [CHOKE-PCMC063T-3R3MN-SMT]  63 86.86 90 bottom
PL17  2.2uh/1.85a_2.5x2x1.2  [L3_2X2_5-1_55]  163.05 47.01 180 bottom
PL18  ev@0.68uh_7x7x3  [CHOKE-PCMC063T-3R3MN-SMT]  219.89 165.88 270 bottom
PL6012  2.2uh_7x7x3  [CHOKE-PCMC063T-3R3MN-SMT]  67.85 47.21 0 bottom
PL6013  1uh_7x7x3  [CHOKE-PCMC063T-3R3MN-SMT]  67.39 32.35 180 bottom
PQ1  aon6414al  [SO-8FL-5P-OA]  153.5 168.78 0 bottom
PQ3  2n7002k  [SOT23_213-3_3-2]  47.55 32.53 270 top
PQ4  *2n7002k  [SOT23_213-3_3-2]  39.12 40.98 270 top
PQ5  2n7002k  [SOT23_213-3_3-2]  70.77 94.08 180 top
PQ6  dtc144eu  [UMT_213-3-1_3]  72.93 106.93 0 top
PQ7  2n7002k  [SOT23_213-3_3-2]  73.97 103.4 180 top
PQ8  2n7002k  [SOT23_213-3_3-2]  70.11 103.14 90 top
PQ9  2n7002k  [SOT23_213-3_3-2]  40.82 116.1 270 top
PQ10  *2n7002k  [SOT23_213-3_3-2]  38.92 32.53 270 top
PQ11  dtc144eu  [UMT_213-3-1_3]  42.47 33.67 270 top
PQ12  ao3409  [SOT23_213-3_3-2]  44.64 113.27 270 top
PQ13  dtc144eu  [UMT_213-3-1_3]  41.08 112.31 90 top
PQ14  2n7002k  [SOT23_213-3_3-2]  46.16 108.22 90 top
PQ15  ev@pdtc143tt  [SOT23_213-3_3-2]  55.2 71.17 270 top
PQ16  ev@2n7002k  [SOT23_213-3_3-2]  196.14 105.81 270 bottom
PQ17  ev@2n7002k  [SOT23_213-3_3-2]  185.83 104.19 0 top
PQ18  *ev@2n7002k  [SOT23_213-3_3-2]  207.07 54.25 270 bottom
PQ19  ev@ao3404  [SOT23_213-3_3-2]  177.73 100.48 0 top
PQ20  aon7410  [WDFN5-3_05X3_05-65]  166.33 183.43 0 top
PQ21  aon7410  [WDFN5-3_05X3_05-65]  170.77 180.36 180 top
PQ22  aon6414al  [SO-8FL-5P-OA]  216.97 189.45 180 bottom
PQ23  ao3404  [SOT23_213-3_3-2]  76.13 99.46 90 bottom
PQ24  aon7410  [WDFN5-3_05X3_05-65]  59.85 66.16 270 bottom
PQ25  aon7752  [WDFN5-3_05X3_05-65]  59.77 60.4 180 bottom
PQ26  mdv1528q  [WDFN5-3_05X3_05-65]  75.98 93.42 0 bottom
PQ27  ev@aon6752  [SO-8FL-5P-OA]  200.97 76.35 180 bottom
PQ30  ev@aon6414al  [SO-8FL-5P-OA]  180.73 70.1 0 bottom
PQ33  ev@aon6414al  [SO-8FL-5P-OA]  209.53 77.24 180 bottom
PQ34  ev@aon6752  [SO-8FL-5P-OA]  188.55 71.29 0 bottom
PQ40  *ev@2n7002k  [SOT23_213-3_3-2]  151.54 174.85 180 top
PQ41  ev@aon6414al  [SO-8FL-5P-OA]  209.53 70.53 180 bottom
PQ42  ev@aon6752  [SO-8FL-5P-OA]  201.02 70.17 180 bottom
PQ43  ev@aon6414al  [SO-8FL-5P-OA]  180.78 76.32 0 bottom
PQ44  ev@aon6752  [SO-8FL-5P-OA]  188.55 77.57 0 bottom
PQ6053  aon7752  [WDFN5-3_05X3_05-65]  60.94 48.36 180 bottom
PQ6054  aon7410  [WDFN5-3_05X3_05-65]  61.07 43.58 0 bottom
PQ6056  aon6978  [POWER-5X6-1_27-7P]  60.03 30.75 90 bottom
PQ6057  *2n7002k  [SOT23_213-3_3-2]  37.65 53.11 270 top
PQ6058  *2n7002k  [SOT23_213-3_3-2]  33.84 53.11 270 top
PQ6065  *ao3404  [SOT23_213-3_3-2]  157.79 42.31 270 bottom
PQ6066  *2n7002k  [SOT23_213-3_3-2]  157.79 36.47 270 bottom
PR1  100k/f_4  [R0402]  161.55 180.61 180 top
PR2  *4.7_6  [R0603]  169.22 182.77 90 bottom
PR3  137k/f_4  [R0402]  154.72 185.24 270 top
PR4  100k/f_4  [R0402]  165.23 181.93 180 bottom
PR5  20_1206  [R1206]  208.59 188.49 270 bottom
PR6  100/f_4  [R0402]  149.97 170.62 90 top
PR7  100/f_4  [R0402]  152.79 170.59 90 top
PR8  100/f_4  [R0402]  155.63 170.56 90 top
PR9  1m_4  [R0402]  155.63 168.88 90 top
PR10  *0_4  [R0402]  157.49 170.83 0 top
PR11  100k_4  [R0402]  151.45 181.33 180 top
PR12  *short_4  [S0402]  152.84 178.35 270 top
PR13  *0_4  [R0402]  151.43 179.34 180 top
PR14  316k/f_4  [R0402]  159.44 176.6 270 top
PR15  100k/f_4  [R0402]  160.38 176.6 270 top
PR16  10k_4  [R0402]  154.06 176.63 90 top
PR17  10/f_6  [R0603]  138.41 169.21 0 bottom
PR18  *gt3@100k/f_4  [R0402]  142.83 172.89 180 bottom
PR19  *gt3@100k/f_6  [R0603]  141.1 166.82 0 bottom
PR20  3.65k/f_6  [R0603]  138.84 167.15 90 bottom
PR21  1k/f_4  [R0402]  142.02 168.78 270 top
PR22  11k/f_4  [R0402]  140.67 170.12 0 top
PR23  2k/f_4  [R0402]  139.02 170.99 90 top
PR24  1k/f_4  [R0402]  137.9 170.99 90 top
PR25  *short_4  [S0402]  136.51 173.37 90 top
PR26  *short_4  [S0402]  144.71 172.69 0 bottom
PR27  *short_4  [S0402]  144.71 172.69 0 top
PR28  *short_4  [S0402]  133.49 171.74 180 top
PR29  *short_4  [S0402]  144.74 173.96 0 top
PR30  *short_4  [S0402]  133.49 172.75 180 top
PR31  *10_4  [R0402]  148.32 177.54 90 top
PR32  *short_4  [S0402]  133.48 173.76 180 top
PR33  *short_4  [S0402]  149.23 175.64 90 top
PR34  499/f_4  [R0402]  147.73 176.14 180 top
PR35  49.9/f_4  [R0402]  133.51 174.7 180 top
PR36  2k/f_4  [R0402]  144.74 176.96 180 top
PR37  *short_4  [S0402]  47.53 46.93 0 top
PR38  *short_4  [S0402]  147.78 173.88 180 top
PR39  *10_4  [R0402]  148.44 172.41 90 top
PR40  10_4  [R0402]  133.52 175.7 0 top
PR41  1k/f_4  [R0402]  147.4 183.03 270 top
PR42  *short_4  [S0402]  142.04 180.74 180 bottom
PR43  *short_4  [S0402]  142.04 181.76 180 bottom
PR44  *2k/f_4  [R0402]  141.36 182.82 270 top
PR45  301/f_4  [R0402]  142.17 183.15 270 bottom
PR46  *short_4  [S0402]  137.19 181.3 270 top
PR47  *short_4  [S0402]  136.18 181.3 270 top
PR48  1k/f_4  [R0402]  138.03 184.53 180 bottom
PR49  *10_4  [R0402]  141.28 187.29 270 bottom
PR50  *short_4  [S0402]  144.76 186.41 180 top
PR51  *10_4  [R0402]  145.27 184.88 90 top
PR52  *short_4  [S0402]  144.76 187.47 180 top
PR53  100k_4  [R0402]  43.87 45.23 0 top
PR54  100k_4  [R0402]  47.12 45.46 90 top
PR55  *short_6  [S0603]  136.48 161.08 270 top
PR56  *short_6  [S0603]  148.44 162.55 270 bottom
PR57  2.2/f_6  [R0603]  121.04 154.55 0 top
PR58  *gt3@2.2/f_6  [R0603]  128.76 154.15 0 top
PR59  2.2/f_6  [R0603]  150.07 153.03 270 top
PR60  2.2/f_6  [R0603]  141.16 153.37 270 top
PR61  *short_6  [S0603]  118.62 162.28 180 top
PR62  *short_6  [S0603]  126.52 161.13 270 top
PR68  *short_4  [S0402]  45.95 51.38 0 top
PR69  *short_4  [S0402]  162.62 62.5 270 bottom
PR73  100k_4  [R0402]  162.36 64.54 90 bottom
PR75  100k_4  [R0402]  161.63 62.1 90 bottom
PR81  *short_4  [S0402]  157.89 61.21 90 bottom
PR82  *short_4  [S0402]  64.04 74.85 90 top
PR83  *short_4  [S0402]  65.54 70.86 90 top
PR84  *ev@100_4  [R0402]  176.21 87.14 90 bottom
PR85  *ev@100_4  [R0402]  173.16 87.14 90 bottom
PR86  5.1k/f_4  [R0402]  62.24 70.91 270 top
PR87  *short_4  [S0402]  64.55 70.86 90 bottom
PR88  10/f_6  [R0603]  66.91 72.99 270 top
PR89  ev@2.2/f_6  [R0603]  198.61 76.52 90 top
PR90  *4.7_6  [R0603]  61.75 59.56 0 top
PR91  ev@2.2/f_6  [R0603]  188.88 71.6 180 top
PR92  20k/f_4  [R0402]  63.2 70.91 90 bottom
PR93  *0_4  [R0402]  64.55 70.86 90 top
PR94  *short_4  [S0402]  66.53 70.84 90 bottom
PR95  ev@2.2/f_6  [R0603]  196.09 62.33 180 bottom
PR96  ev@2.2/f_6  [R0603]  203.54 62.28 0 bottom
PR97  73.2k/f_4  [R0402]  62.24 70.91 270 bottom
PR98  *4.7_6  [R0603]  64.7 83.71 0 top
PR99  2.2/f_6  [R0603]  68.43 76.09 270 bottom
PR100  ev@20k/f_4  [R0402]  220.33 177.72 90 bottom
PR101  *ev@10k_4  [R0402]  206.08 60.68 0 bottom
PR102  *ev@0_4  [R0402]  206.05 58.67 180 bottom
PR103  *ev@0_4  [R0402]  218.34 175.94 0 top
PR104  *ev@10k_4  [R0402]  206.08 59.68 0 bottom
PR105  *ev@5.1k/f_4  [R0402]  206.63 57.2 90 bottom
PR106  ev@20k/f_4  [R0402]  204.17 57.55 180 bottom
PR107  100k/f_4  [R0402]  41.81 51.51 0 top
PR108  ev@14k/f_4  [R0402]  220.35 179.27 0 bottom
PR109  *short_4  [S0402]  219.13 177.74 90 bottom
PR110  *short_4  [S0402]  216.85 177.57 270 bottom
PR111  ev@10/f_6  [R0603]  216.67 175.81 90 top
PR112  ev@0_4  [R0402]  204.15 54.5 180 bottom
PR113  ev@20k/f_4  [R0402]  200.01 55.98 90 bottom
PR114  ev@18k/f_4  [R0402]  204.09 55.98 90 bottom
PR115  ev@2k/f_4  [R0402]  202.14 55.98 270 bottom
PR116  ev@73.2k/f_4  [R0402]  221.8 177.34 0 bottom
PR117  *short_4  [S0402]  217.99 173.37 270 top
PR118  ev@16k/f_6  [R0603]  193.5 59.84 90 bottom
PR119  34k/f_4  [R0402]  37.42 46.76 90 top
PR120  *ev@4.7_6  [R0603]  218.62 169.69 270 top
PR121  30k/f_4  [R0402]  37.47 48.59 90 top
PR122  *short_4  [S0402]  218.27 177.74 270 top
PR123  ev@2.2/f_6  [R0603]  215.09 173.25 0 bottom
PR133  34k/f_4  [R0402]  160.53 72.03 180 bottom
PR135  **gt3@100k/f_4  [R0402]  50.37 83.71 180 bottom
PR136  *short_4  [S0402]  50.32 83.15 180 top
PR137  *22_8  [R0805]  39.51 44.02 0 top
PR138  22_8  [R0805]  75.48 94.23 0 top
PR139  22_8  [R0805]  76.43 105.66 0 top
PR140  1m_6  [R0603]  69.53 107.59 0 top
PR141  1m_6  [R0603]  69.53 106.06 180 top
PR142  1m_6  [R0603]  67.49 102.92 90 top
PR143  *short_6  [S0603]  200.41 64.84 90 bottom
PR144  200k/f_4  [R0402]  51.85 106.44 270 top
PR145  200k/f_4  [R0402]  52.94 106.44 270 top
PR146  1.47k/f_4  [R0402]  50.76 106.41 270 top
PR147  *100k/f_6  [R0603]  42.47 31.26 180 top
PR148  1m_6  [R0603]  46.28 35.71 90 top
PR150  1m_6  [R0603]  44.76 32.66 90 top
PR151  1m_6  [R0603]  44.76 35.71 90 top
PR152  1m_6  [R0603]  44.51 110.76 0 top
PR153  *220_8  [R0805]  38.92 36.09 90 top
PR154  *short_6  [S0603]  48.02 115.36 180 top
PR155  200k_6  [R0603]  48.69 112.9 90 top
PR156  43.2k/f_4  [R0402]  160.48 73.02 180 bottom
PR157  ev@1m_6  [R0603]  57.26 72.74 180 top
PR158  ev@100k_4  [R0402]  52.15 69.13 0 top
PR159  ev@1m_6  [R0603]  52.74 72.69 180 top
PR160  *short_4  [S0402]  52.15 71.11 180 top
PR161  ev@1m_6  [R0603]  197.29 108.35 0 bottom
PR162  *short_4  [S0402]  174.17 87.14 90 bottom
PR163  *short_4  [S0402]  175.19 87.14 90 bottom
PR164  ev@22_8  [R0805]  182.25 104.11 180 top
PR165  4.02k/f_4  [R0402]  157.33 186.96 90 top
PR166  4.02k/f_4  [R0402]  158.32 186.94 90 top
PR167  *short_4  [S0402]  156.39 186.95 90 top
PR168  866k/f_4  [R0402]  155.4 186.94 90 top
PR169  0.01/f_0612  [RC3216]  168.51 175.08 90 bottom
PR170  *short_4  [S0402]  154.41 186.94 90 top
PR171  *short_4  [S0402]  151.54 186.94 90 top
PR172  *short_4  [S0402]  151.47 185.19 180 top
PR173  *short_6  [S0603]  161.77 181.83 0 top
PR174  *100k_4  [R0402]  151.47 184.22 0 top
PR175  *short_4  [S0402]  165.99 176.7 180 bottom
PR176  *short_4  [S0402]  165.99 177.67 180 bottom
PR177  *short_4  [S0402]  151.48 183.28 180 top
PR178  *short_4  [S0402]  151.48 182.32 180 top
PR179  *10k_4  [R0402]  151.47 180.31 0 top
PR180  *10_4  [R0402]  138.74 166.85 180 top
PR181  *short_4  [S0402]  135.06 166.36 180 top
PR182  *gt3@10/f_6  [R0603]  141.13 170.1 180 bottom
PR183  10/f_6  [R0603]  157.99 176.4 270 top
PR184  10/f_6  [R0603]  156.6 176.4 270 top
PR185  *short_6  [S0603]  156.55 166.29 0 top
PR186  10/f_6  [R0603]  155.23 176.19 270 top
PR187  *10_4  [R0402]  134.98 168.35 0 top
PR188  *gt3@100k/f_4  [R0402]  143.19 170.99 270 bottom
PR189  *gt3@100k/f_6  [R0603]  143.9 168.98 90 bottom
PR190  *gt3@3.65k/f_6  [R0603]  141.13 168.47 180 bottom
PR191  *short_4  [S0402]  135.03 167.33 180 top
PR192  sp@267/f_4  [R0402]  141.43 171.37 180 bottom
PR193  2.61k/f_4  [R0402]  139.05 170.99 90 bottom
PR194  sp@1.91k/f_4  [R0402]  137.9 170.99 90 bottom
PR195  3k/f_4  [R0402]  136.91 170.99 90 bottom
PR196  *10k/f_4  [R0402]  133.53 172.1 0 bottom
PR197  10k/f_4  [R0402]  133.53 173.12 0 bottom
PR198  sp@88.7k/f_4  [R0402]  137.5 174.64 270 bottom
PR199  4.87k/f_4  [R0402]  144.74 175.94 180 top
PR200  *10k/f_4  [R0402]  133.53 174.01 0 bottom
PR201  sp@1.37k/f_4  [R0402]  146.21 177.11 270 top
PR202  sp@88.7k/f_4  [R0402]  141.17 176.18 0 bottom
PR203  sp@78.7k/f_4  [R0402]  137.23 178.19 180 bottom
PR204  1/f_6  [R0603]  133.41 177.18 180 top
PR205  2.61k/f_4  [R0402]  147.53 181.1 270 top
PR206  63.4k/f_4  [R0402]  135.72 179.57 0 top
PR207  sp@162k_4  [R0402]  140.39 179.12 90 bottom
PR208  11k/f_4  [R0402]  148.88 184.12 90 top
PR209  10_4  [R0402]  207.9 184.12 0 bottom
PR210  10_4  [R0402]  207.89 185.16 0 bottom
PR211  sp@237/f_4  [R0402]  145.93 183.48 180 top
PR212  *short_8  [S0805]  133.79 177.41 0 bottom
PR213  0.01/f_0612  [RC3216]  210.72 184.55 180 bottom
PR214  10/f_6  [R0603]  147.66 179.34 180 top
PR215  3.65k/f_6  [R0603]  148.7 181.88 90 top
PR216  2.49k/f_4  [R0402]  142.42 182.82 270 top
PR217  2.05k/f_4  [R0402]  141.15 183.15 270 bottom
PR218  2.61k/f_4  [R0402]  139.25 183.41 180 top
PR219  11k/f_4  [R0402]  139.25 182.44 180 bottom
PR220  475/f_4  [R0402]  137.62 183.1 270 top
PR221  10/f_6  [R0603]  138.84 187.45 180 bottom
PR222  3.65k/f_6  [R0603]  139.71 185.49 270 bottom
PR223  *short_6  [S0603]  121.38 163.81 90 bottom
PR224  13.7k/f_4  [R0402]  136.89 164.38 270 bottom
PR225  13.7k/f_4  [R0402]  125.84 161.89 180 bottom
PR226  27.4k/f_4  [R0402]  125.46 163.24 90 bottom
PR227  470k_4_4700ntc  [R0402]  126.45 163.24 90 bottom
PR228  *short_4  [S0402]  119.22 163.35 90 bottom
PR229  *short_4  [S0402]  120.19 163.38 90 bottom
PR230  *short_6  [S0603]  129.6 163.67 90 bottom
PR231  *short_6  [S0603]  140.98 163.47 90 bottom
PR232  *short_6  [S0603]  152.08 163.7 90 bottom
PR233  *gt3@0_4  [R0402]  127.43 163.23 90 bottom
PR234  *gt3@0_4  [R0402]  128.44 163.23 90 bottom
PR235  27.4k/f_4  [R0402]  137.27 163.01 0 bottom
PR236  470k_4_4700ntc  [R0402]  137.24 162.05 0 bottom
PR237  *short_4  [S0402]  138.87 163.04 90 bottom
PR238  *short_4  [S0402]  139.85 163.05 90 bottom
PR239  *short_4  [S0402]  149.82 163.55 90 bottom
PR240  *short_4  [S0402]  150.83 163.55 90 bottom
PR241  10k/f_4_3435ntc  [R0402]  115.6 152.47 90 bottom
PR242  10k/f_4_3435ntc  [R0402]  147.48 152.98 90 bottom
PR243  10k/f_4_3435ntc  [R0402]  134.45 152.24 270 bottom
PR250  232k/f_4  [R0402]  48.55 57.55 90 top
PR251  2.2/f_6  [R0603]  45.55 60.88 0 top
PR252  *short_4  [S0402]  191.73 61.21 0 bottom
PR253  *ev@0_4  [R0402]  206.23 64.1 0 bottom
PR254  *short_4  [S0402]  67.29 59.33 0 top
PR255  *short_4  [S0402]  204.15 59.58 0 bottom
PR256  *short_4  [S0402]  204.15 58.67 0 bottom
PR257  *short_4  [S0402]  40.57 53.61 0 top
PR258  7.87k/f_4  [R0402]  40.98 54.83 270 top
PR259  ev@10k_4  [R0402]  191.75 60.14 0 bottom
PR260  *ev@1/f_4  [R0402]  197.41 53.99 270 bottom
PR261  499k/f_4  [R0402]  44.96 52.93 90 top
PR262  10k/f_4_3435ntc  [R0402]  36.12 114.07 180 bottom
PR263  *short_4  [S0402]  44 52.93 90 top
PR264  *short_4  [S0402]  49.05 55.09 180 top
PR265  *0_4  [R0402]  47.68 54.93 90 top
PR266  10k/f_4  [R0402]  39.63 54.45 0 top
PR267  *short_4  [S0402]  45.95 52.93 90 top
PR268  ev@24.9k/f_4  [R0402]  197.14 55.98 90 bottom
PR269  100/f_4  [R0402]  40.34 56.36 0 top
PR270  ev@13k/f_4  [R0402]  199.04 55.98 90 bottom
PR271  10k_4  [R0402]  169.22 45.49 180 bottom
PR273  *short_4  [S0402]  171.02 47.77 90 bottom
PR274  *short_4  [S0402]  49.05 56.08 0 top
PR275  *ev@499k/f_4  [R0402]  198.08 55.98 270 bottom
PR276  ev@100k/f_4  [R0402]  206.23 62.17 0 bottom
PR277  *short_4  [S0402]  194.42 57.73 180 bottom
PR278  47.5k/f_4  [R0402]  169.73 48.36 0 bottom
PR279  *short_4  [S0402]  194.42 55.82 180 bottom
PR280  *short_4  [S0402]  48.44 84.47 180 top
PR281  *short_4  [S0402]  40.09 58.41 0 top
PR285  *short_6  [S0603]  165.28 50.95 180 bottom
PR286  *short_4  [S0402]  50.3 81.5 0 bottom
PR287  *short_4  [S0402]  50.32 82.57 0 bottom
PR288  *short_4  [S0402]  50.32 84.68 180 bottom
PR289  *gt3@100k/f_4  [R0402]  50.3 85.64 180 bottom
PR290  *short_4  [S0402]  57.69 81.17 0 bottom
PR291  *short_6  [S0603]  56.5 84.58 0 bottom
PR292  *short_4  [S0402]  58.15 82.9 90 bottom
PR293  *gt3@100k/f_4  [R0402]  57.71 81.17 0 top
PR294  *short_6  [S0603]  54.9 81.15 180 top
PR295  100k/f_4  [R0402]  67.49 70.84 270 bottom
PR296  ev@100k/f_4  [R0402]  215.88 177.57 90 bottom
PR302  15k/f_4  [R0402]  169.73 49.42 0 bottom
PR304  *0_4  [R0402]  47.71 62.05 0 top
PR306  *short_4  [S0402]  167.57 50.44 0 bottom
PR307  *short_4  [S0402]  171.25 45.61 270 bottom
PR309  ev@10k/f_4  [R0402]  204.68 176.52 0 bottom
PR310  ev@7.5k/f_4  [R0402]  204.65 175.53 180 bottom
PR311  *short_4  [S0402]  203.16 174.19 90 bottom
PR312  ev@10/f_6  [R0603]  207.55 178.33 0 bottom
PR314  100k/f_4  [R0402]  169.73 50.44 180 bottom
PR317  *short_4  [S0402]  204.63 172.41 180 top
PR318  *ev@100k/f_4  [R0402]  202.85 172.38 0 top
PR319  *ev@2.2/f_6  [R0603]  211.44 172.71 270 bottom
PR321  *short_4  [S0402]  204.63 172.41 0 bottom
PR340  100/f_4  [R0402]  131.5 175.15 180 top
PR341  45.3/f_4  [R0402]  131.5 174.14 180 top
PR342  sp@12.7k/f_4  [R0402]  135.79 170.99 270 top
PR344  *gt3@10/f_4  [R0402]  54.08 82.37 180 top
PR345  *short_4  [S0402]  206.23 63.11 0 bottom
PR1247  *short_8  [S0805]  35.24 49.42 0 top
PR1248  *short_8  [S0805]  48.16 48.56 0 top
PR1249  *short_8  [S0805]  158.55 73.68 270 bottom
PR1250  *short_8  [S0805]  159.8 57.75 270 bottom
PR6120  10k/f_4  [R0402]  56.04 38.4 180 top
PR6121  10k/f_4  [R0402]  56.04 39.42 180 top
PR6122  113k/f_4  [R0402]  54.97 40.96 0 top
PR6124  49.9k/f_4  [R0402]  55.94 36.34 180 top
PR6125  *short_6  [S0603]  56.14 37.46 270 bottom
PR6130  *short_6  [S0603]  48.82 41.29 90 top
PR6278  *short_4  [S0402]  53.22 35.15 90 top
PR6279  6.49k/f_4  [R0402]  55.89 40.81 0 bottom
PR6280  10k/f_4  [R0402]  55.89 41.8 0 bottom
PR6281  15.8k/f_4  [R0402]  56.06 37.38 180 top
PR6282  *short_4  [S0402]  66.73 20.62 0 bottom
PR6283  *short_4  [S0402]  54.9 42.97 180 top
PR6284  10k/f_4  [R0402]  53.42 43.43 90 top
PR6285  *short_4  [S0402]  66.73 22.55 0 bottom
PR6286  1/f_6  [R0603]  50.86 42.18 0 top
PR6287  1/f_6  [R0603]  50.53 35.1 180 top
PR6288  *4.7_6  [R0603]  64.78 27.07 90 bottom
PR6289  *4.7_6  [R0603]  63.51 49.07 0 top
PR6290  *10k_4  [R0402]  40.06 52.34 90 top
PR6291  *short_4  [S0402]  66.73 19.65 180 bottom
PR6292  *short_4  [S0402]  59.54 54.55 180 top
PR6293  *short_4  [S0402]  61.68 55.57 0 top
PR6294  *short_4  [S0402]  61.7 53.49 180 top
PR6295  *0_6  [R0603]  75.37 50.95 90 bottom
PR6296  0_6  [R0603]  59.72 38.2 180 bottom
PR6297  100k_4  [R0402]  54.95 41.98 180 top
PR6298  *22_8  [R0805]  157.54 39.39 180 bottom
PR6299  *short_4  [S0402]  38.92 93.87 270 top
PR6300  *short_4  [S0402]  40.95 93.87 270 top
PR6301  sp@0_4  [R0402]  145.22 170.99 90 top
PR6302  *0_4  [R0402]  45.47 62.07 180 top
PR6303  *0_4  [R0402]  42.32 54.45 0 top
PR6304  *short_37  [SHORT3720]  133.84 162.2 180 bottom
PR6306  *short_8  [S0805]  71.76 100.07 180 bottom
PR6307  *short_8  [S0805]  69.07 97.35 180 bottom
PU1  isl95859hrtz-t  [QFN40-5X5-4-41P-ISL62771-SMT]  139.2 176.92 0 top
PU2  yb1282psp8  [SOP8-6-1_27-9P]  42.04 48.44 90 top
PU4  as393mtr-e1  [SOIC8-6-1_27]  52.05 111.91 0 top
PU5  bq24780sruyr  [QFN28-4X4-4-38P]  156.72 181.71 180 top
PU6  yb1282psp8  [SOP8-6-1_27-9P]  159.19 67.38 180 bottom
PU7  *gt3@aoz5049qi  [POWER-3_5X5-5-14P]  129.58 158.73 0 bottom
PU8  aoz5049qi  [POWER-3_5X5-5-14P]  139.47 158.53 0 bottom
PU9  aoz5029qi-5  [POWER-3_5X5-5-14P]  151.49 159.1 0 bottom
PU10  apl3523a  [SON14-3X2-4-15P]  58.78 54.45 270 bottom
PU11  apl3523a  [SON14-3X2-4-15P]  63.66 20.82 270 bottom
PU13  aoz5049qi  [POWER-3_5X5-5-14P]  119.89 158.77 0 bottom
PU14  *gt3@nb681gd-z  [QFN13-2X3-5]  53.85 82.62 180 bottom
PU15  g5335qt2u  [QFN23-4X4-5-25P]  64.29 75.1 180 bottom
PU16  g5719ctb1u  [TSOP6-2_8-95]  167.04 47.98 270 bottom
PU18  ev@rt8068azqw  [DFN10-3X3-5-11P-RT9296]  207.4 175.05 180 bottom
PU19  ev@up1658rqkf  [QFN20-3X3-4-21P-0_8H]  199.85 60.14 270 bottom
PU20  apl3523a  [SON14-3X2-4-15P]  39.3 97.43 0 top
PU21  rt8231bgqw  [WQFN20-3X3-4-21P]  44.76 56.56 270 top
PU22  ev@g5335qt2u  [QFN23-4X4-5-25P]  219.82 173.78 0 bottom
PU6010  rt6575agqw  [QFN20-3X3-4-26P]  52.41 38.73 90 top
Q1  *tsi@2n7002k  [SOT23_213-3_3-2]  133.08 179.75 90 top
Q2  *tsi@2n7002dw  [SC70-2_1-65-6P]  119.18 175.03 180 top
Q3  2n7002dw  [SC70-2_1-65-6P]  108.01 152.67 270 bottom
Q4  dtc144eua  [UMT_213-3-1_3]  111.18 156.23 0 bottom
Q5  mmbt3904-7-f  [SOT23_213-3_3-2]  92.51 129.31 90 bottom
Q15  tyc@2n7002k  [SOT23_213-3_3-2]  26.22 104.92 0 top
Q17  tyc@2n7002k  [SOT23_213-3_3-2]  23.04 107.46 0 top
Q18  kbl@ao3413  [SOT23_213-3_3-2]  225.99 124.76 270 bottom
Q19  kbl@dtc144eu  [UMT_213-3-1_3]  225.99 119.4 0 bottom
Q20  *tdi@2n7002k  [SOT23_213-3_3-2]  151.82 118.89 90 bottom
Q21  ap2331sa-7  [SOT23_213-3_3-2]  12.63 85.49 270 bottom
